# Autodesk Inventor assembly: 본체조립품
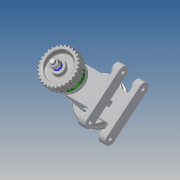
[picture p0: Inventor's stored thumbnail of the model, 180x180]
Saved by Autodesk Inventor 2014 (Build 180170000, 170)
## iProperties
Created: 2015-11
Part Number: 본체조립품
Document SubType Name: Assembly
Designer: Owner
Author: Owner
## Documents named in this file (15)
- C:\Documents and Settings\Owner\바탕 화면\451109V1014\본체조립품.iam
- C:\Documents and Settings\Owner\바탕 화면\451109V1014\본체.ipt
- C:\Documents and Settings\Owner\바탕 화면\451109V1014\커버.ipt
- C:\Documents and Settings\Owner\바탕 화면\451109V1014\베어링 15 x 32 x 9.ipt
- C:\Documents and Settings\Owner\바탕 화면\451109V1014\오일 실 15 25 7.ipt
- C:\Documents and Settings\Owner\바탕 화면\451109V1014\볼트 M4 x 12.ipt
- C:\Documents and Settings\Owner\바탕 화면\451109V1014\축.ipt
- C:\Documents and Settings\Owner\바탕 화면\451109V1014\키 3 x 3 x 12.ipt
- C:\Documents and Settings\Owner\바탕 화면\451109V1014\스퍼기어.ipt
- C:\Documents and Settings\Owner\바탕 화면\451109V1014\V벨트풀리.ipt
- C:\Documents and Settings\Owner\바탕 화면\451109V1014\와셔 6x11.5.ipt
- C:\Documents and Settings\Owner\바탕 화면\451109V1014\스프링와셔 8.ipt
- C:\Documents and Settings\Owner\바탕 화면\451109V1014\너트 M 8.ipt
- C:\Documents and Settings\Owner\바탕 화면\451109V1014\볼트 M 6 x 8.ipt
- C:\Documents and Settings\Owner\바탕 화면\451109V1014\니플 M 6 x 0.75.ipt
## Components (11 placed, 3 different names)
1. KS B 2023 6002 - 15 x 32 x 9:1
2. KS B 2023 6002 - 15 x 32 x 9:2
3. V벨트풀리:1
4. ISO 4762 M4 x 12:2
5. ISO 4762 M4 x 12:3
6. ISO 4762 M4 x 12:4
7. ISO 4762 M4 x 12:5
8. ISO 4762 M4 x 12:1
9. ISO 4762 M4 x 12:6
10. ISO 4762 M4 x 12:7
11. ISO 4762 M4 x 12:8
